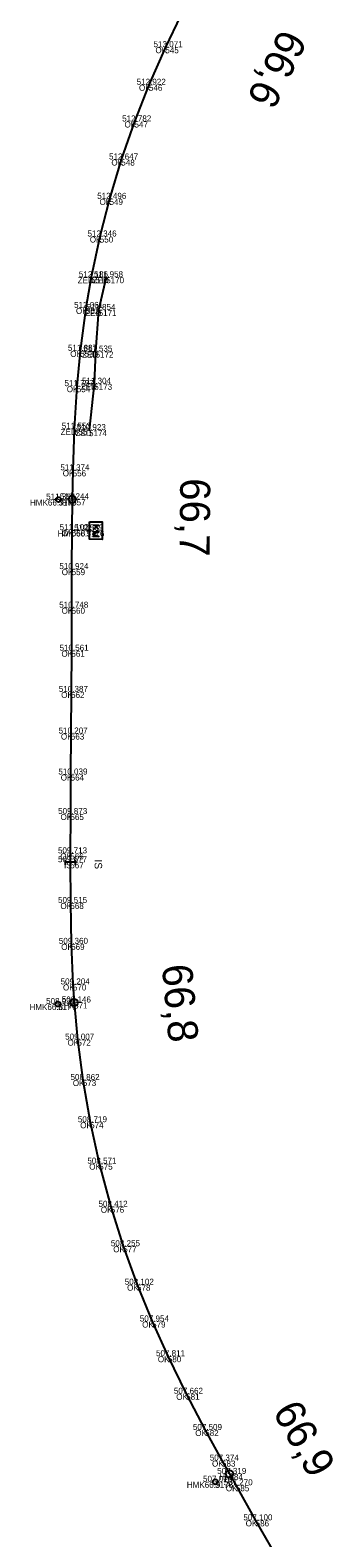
# Model space of a CAD drawing. Extents: x -621782 to -610392, y -1141853 to -1122321.
# Drawn here: x -621541.5 to -621480.9, y -1123820.3 to -1123519.4 of the extents above; entities that cross this region are included whole.
import ezdxf

# ---------------------------------------------------------------- set-up
doc = ezdxf.new("R2010")
doc.units = 0
for name, color, linetype in [('Vrstva 1', 7, 'Continuous'), ('Vrstva 13', 7, 'Continuous'), ('Vrstva 3', 7, 'Continuous'), ('Vrstva 60', 7, 'Continuous'), ('Vrstva 61', 7, 'Continuous'), ('Vrstva 62', 7, 'Continuous'), ('Vrstva 7', 7, 'Continuous')]:
    doc.layers.add(name, color=color, linetype=linetype)

msp = doc.modelspace()

# ---------------------------------------------------------------- linework, layer by layer
at = {"layer": 'Vrstva 1'}
msp.add_lwpolyline([(-621511.47, -1123516.54), (-621514.51, -1123522.8), (-621517.78, -1123530.3), (-621520.67, -1123537.63), (-621523.29, -1123545.22), (-621525.64, -1123553.07), (-621527.58, -1123560.59), (-621529.29, -1123568.71), (-621530.35, -1123574.84), (-621531.48, -1123583.41), (-621532.17, -1123590.46), (-621532.72, -1123598.98), (-621532.98, -1123607.26), (-621533.09, -1123613.05), (-621533.15, -1123619.2), (-621533.19, -1123626.98), (-621533.21, -1123634.69), (-621533.25, -1123643.27), (-621533.3, -1123651.49), (-621533.35, -1123659.8), (-621533.39, -1123667.98), (-621533.43, -1123675.87), (-621533.46, -1123683.72), (-621533.47, -1123685.49), (-621533.45, -1123693.62), (-621533.29, -1123701.78), (-621532.94, -1123709.88), (-621532.7, -1123713.48), (-621532.04, -1123720.89), (-621530.97, -1123728.96), (-621529.5, -1123737.38), (-621527.7, -1123745.65), (-621525.39, -1123754.26), (-621522.92, -1123762.13), (-621520.16, -1123769.81), (-621517.15, -1123777.16), (-621514.02, -1123784.08), (-621510.36, -1123791.59), (-621506.56, -1123798.82), (-621503.22, -1123804.92), (-621501.73, -1123807.58), (-621500.46, -1123809.84), (-621496.51, -1123816.85), (-621492.58, -1123823.83)], dxfattribs=at)
at = {"layer": 'Vrstva 13'}
msp.add_lwpolyline([(-621526.3, -1123568.71), (-621527.81, -1123575.26), (-621528.42, -1123583.55), (-621528.69, -1123589.99), (-621529.72, -1123599.24)], dxfattribs=at)
at = {"layer": 'Vrstva 3'}
for p, q in [((-621534.47, -1123684.99), (-621534.47, -1123685.99)), ((-621532.47, -1123685.48), (-621534.47, -1123685.49)), ((-621532.47, -1123684.98), (-621532.47, -1123685.98))]:
    msp.add_line(p, q, dxfattribs=at)
at = {"layer": 'Vrstva 60'}
for p, q in [((-621514.51, -1123522.8), (-621514.51, -1123522.8)), ((-621517.78, -1123530.3), (-621517.78, -1123530.3)), ((-621520.67, -1123537.63), (-621520.67, -1123537.63)), ((-621523.29, -1123545.22), (-621523.29, -1123545.22)), ((-621525.64, -1123553.07), (-621525.64, -1123553.07)), ((-621527.58, -1123560.59), (-621527.58, -1123560.59)), ((-621529.29, -1123568.71), (-621529.29, -1123568.71)), ((-621526.3, -1123568.71), (-621526.3, -1123568.71)), ((-621530.35, -1123574.84), (-621530.35, -1123574.84)), ((-621527.81, -1123575.26), (-621527.81, -1123575.26)), ((-621531.48, -1123583.41), (-621531.48, -1123583.41)), ((-621528.42, -1123583.55), (-621528.42, -1123583.55)), ((-621532.17, -1123590.46), (-621532.17, -1123590.46)), ((-621528.69, -1123589.99), (-621528.69, -1123589.99)), ((-621532.72, -1123598.98), (-621532.72, -1123598.98)), ((-621529.72, -1123599.24), (-621529.72, -1123599.24)), ((-621532.98, -1123607.26), (-621532.98, -1123607.26)), ((-621535.82, -1123613.09), (-621535.82, -1123613.09)), ((-621533.09, -1123613.05), (-621533.09, -1123613.05)), ((-621533.15, -1123619.2), (-621533.15, -1123619.2)), ((-621530.23, -1123619.27), (-621530.23, -1123619.27)), ((-621533.19, -1123626.98), (-621533.19, -1123626.98)), ((-621533.21, -1123634.69), (-621533.21, -1123634.69)), ((-621533.25, -1123643.27), (-621533.25, -1123643.27)), ((-621533.3, -1123651.49), (-621533.3, -1123651.49)), ((-621533.35, -1123659.8), (-621533.35, -1123659.8)), ((-621533.39, -1123667.98), (-621533.39, -1123667.98)), ((-621533.43, -1123675.87), (-621533.43, -1123675.87)), ((-621533.46, -1123683.72), (-621533.46, -1123683.72)), ((-621533.47, -1123685.49), (-621533.47, -1123685.49)), ((-621533.45, -1123693.62), (-621533.45, -1123693.62)), ((-621533.29, -1123701.78), (-621533.29, -1123701.78)), ((-621532.94, -1123709.88), (-621532.94, -1123709.88)), ((-621535.92, -1123713.79), (-621535.92, -1123713.79)), ((-621532.7, -1123713.48), (-621532.7, -1123713.48)), ((-621532.04, -1123720.89), (-621532.04, -1123720.89)), ((-621530.97, -1123728.96), (-621530.97, -1123728.96)), ((-621529.5, -1123737.38), (-621529.5, -1123737.38)), ((-621527.7, -1123745.65), (-621527.7, -1123745.65)), ((-621525.39, -1123754.26), (-621525.39, -1123754.26)), ((-621522.92, -1123762.13), (-621522.92, -1123762.13)), ((-621520.16, -1123769.81), (-621520.16, -1123769.81)), ((-621517.15, -1123777.16), (-621517.15, -1123777.16)), ((-621514.02, -1123784.08), (-621514.02, -1123784.08)), ((-621510.36, -1123791.59), (-621510.36, -1123791.59)), ((-621506.56, -1123798.82), (-621506.56, -1123798.82)), ((-621503.22, -1123804.92), (-621503.22, -1123804.92)), ((-621501.73, -1123807.58), (-621501.73, -1123807.58)), ((-621504.56, -1123809.16), (-621504.56, -1123809.16)), ((-621500.46, -1123809.84), (-621500.46, -1123809.84)), ((-621496.51, -1123816.85), (-621496.51, -1123816.85))]:
    msp.add_line(p, q, dxfattribs=at)
at = {"layer": 'Vrstva 7'}
for p, q in [((-621535.82, -1123613.04), (-621535.82, -1123613.14)), ((-621527.73, -1123618.27), (-621528.98, -1123618.26)), ((-621527.74, -1123619.1), (-621528.57, -1123618.27)), ((-621530.23, -1123619.27), (-621529.61, -1123619.28)), ((-621528.27, -1123618.57), (-621528.98, -1123619.1)), ((-621535.92, -1123713.74), (-621535.91, -1123713.84)), ((-621504.59, -1123809.12), (-621504.54, -1123809.21))]:
    msp.add_line(p, q, dxfattribs=at)
msp.add_lwpolyline([(-621529.6, -1123617.53), (-621527.11, -1123617.55), (-621527.13, -1123621.04), (-621529.61, -1123621.02)], close=True, dxfattribs=at)
msp.add_lwpolyline([(-621528.99, -1123619.51), (-621527.74, -1123619.52), (-621528.99, -1123619.99), (-621527.75, -1123620.47), (-621528.99, -1123620.46)], dxfattribs=at)
for centre, radius in [((-621533.09, -1123613.05), 0.75), ((-621535.82, -1123613.09), 0.5), ((-621535.92, -1123713.79), 0.5), ((-621532.7, -1123713.48), 0.75), ((-621501.73, -1123807.58), 0.75), ((-621504.56, -1123809.16), 0.5)]:
    msp.add_circle(centre, radius, dxfattribs=at)

# ---------------------------------------------------------------- texts
at = {"layer": 'Vrstva 3'}
msp.add_text('IS', height=1.5, rotation=270.169, dxfattribs=at).set_placement((-621528.62, -1123684.95))
at = {"layer": 'Vrstva 60'}
for s, p in [('545', (-621514.51, -1123524)), ('546', (-621517.78, -1123531.5)), ('547', (-621520.67, -1123538.83)), ('548', (-621523.29, -1123546.42)), ('549', (-621525.64, -1123554.27)), ('550', (-621527.58, -1123561.79)), ('551', (-621529.29, -1123569.91)), ('5170', (-621526.3, -1123569.91)), ('552', (-621530.35, -1123576.04)), ('5171', (-621527.81, -1123576.46)), ('553', (-621531.48, -1123584.61)), ('5172', (-621528.42, -1123584.75)), ('554', (-621532.17, -1123591.66)), ('5173', (-621528.69, -1123591.19)), ('555', (-621532.72, -1123600.18)), ('5174', (-621529.72, -1123600.44)), ('556', (-621532.98, -1123608.46)), ('5175', (-621535.82, -1123614.29)), ('557', (-621533.09, -1123614.25)), ('558', (-621533.15, -1123620.4)), ('5176', (-621530.23, -1123620.47)), ('559', (-621533.19, -1123628.18)), ('560', (-621533.21, -1123635.89)), ('561', (-621533.25, -1123644.47)), ('562', (-621533.3, -1123652.69)), ('563', (-621533.35, -1123661)), ('564', (-621533.39, -1123669.18)), ('565', (-621533.43, -1123677.07)), ('566', (-621533.46, -1123684.92)), ('567', (-621533.47, -1123686.69)), ('568', (-621533.45, -1123694.82)), ('569', (-621533.29, -1123702.98)), ('570', (-621532.94, -1123711.08)), ('5177', (-621535.92, -1123714.99)), ('571', (-621532.7, -1123714.68)), ('572', (-621532.04, -1123722.09)), ('573', (-621530.97, -1123730.16)), ('574', (-621529.5, -1123738.58)), ('575', (-621527.7, -1123746.85)), ('576', (-621525.39, -1123755.46)), ('577', (-621522.92, -1123763.33)), ('578', (-621520.16, -1123771.01)), ('579', (-621517.15, -1123778.36)), ('580', (-621514.02, -1123785.28)), ('581', (-621510.36, -1123792.79)), ('582', (-621506.56, -1123800.02)), ('583', (-621503.22, -1123806.12)), ('584', (-621501.73, -1123808.78)), ('5178', (-621504.56, -1123810.36)), ('585', (-621500.46, -1123811.04)), ('586', (-621496.51, -1123818.05))]:
    msp.add_text(s, height=1.2, dxfattribs=at).set_placement(p)
at = {"layer": 'Vrstva 61'}
for s, p in [('513.071', (-621516.87, -1123522.8)), ('512.922', (-621520.23, -1123530.3)), ('512.782', (-621523.12, -1123537.63)), ('512.647', (-621525.74, -1123545.22)), ('512.496', (-621528.09, -1123553.07)), ('512.346', (-621530.03, -1123560.59)), ('512.186', (-621531.75, -1123568.71)), ('511.958', (-621528.75, -1123568.71)), ('512.061', (-621532.71, -1123574.84)), ('511.854', (-621530.26, -1123575.26)), ('511.887', (-621533.93, -1123583.41)), ('511.535', (-621530.88, -1123583.55)), ('511.737', (-621534.62, -1123590.46)), ('511.304', (-621531.14, -1123589.99)), ('511.553', (-621535.17, -1123598.98)), ('510.923', (-621532.18, -1123599.24)), ('511.374', (-621535.44, -1123607.26)), ('511.354', (-621538.27, -1123613.09)), ('511.244', (-621535.54, -1123613.05)), ('511.102', (-621535.59, -1123619.2)), ('510.539', (-621532.68, -1123619.27)), ('510.924', (-621535.64, -1123626.98)), ('510.748', (-621535.67, -1123634.69)), ('510.561', (-621535.61, -1123643.27)), ('510.387', (-621535.75, -1123651.49)), ('510.207', (-621535.8, -1123659.8)), ('510.039', (-621535.84, -1123667.98)), ('509.873', (-621535.88, -1123675.87)), ('509.677', (-621535.92, -1123685.49)), ('509.713', (-621535.92, -1123683.72)), ('509.515', (-621535.91, -1123693.62)), ('509.360', (-621535.74, -1123701.78)), ('509.204', (-621535.39, -1123709.88)), ('508.931', (-621538.28, -1123713.79)), ('509.146', (-621535.15, -1123713.48)), ('509.007', (-621534.49, -1123720.89)), ('508.862', (-621533.42, -1123728.96)), ('508.719', (-621531.95, -1123737.38)), ('508.571', (-621530.06, -1123745.65)), ('508.412', (-621527.84, -1123754.26)), ('508.255', (-621525.37, -1123762.13)), ('508.102', (-621522.61, -1123769.81)), ('507.954', (-621519.6, -1123777.16)), ('507.811', (-621516.38, -1123784.08)), ('507.662', (-621512.81, -1123791.59)), ('507.509', (-621509.02, -1123798.82)), ('507.374', (-621505.67, -1123804.92)), ('507.010', (-621507.01, -1123809.16)), ('507.319', (-621504.18, -1123807.58)), ('507.270', (-621502.91, -1123809.84)), ('507.100', (-621498.96, -1123816.85))]:
    msp.add_text(s, height=1.2, dxfattribs=at).set_placement(p)
at = {"layer": 'Vrstva 62'}
for s, p in [('OK', (-621516.49, -1123524)), ('OK', (-621519.77, -1123531.5)), ('OK', (-621522.65, -1123538.83)), ('OK', (-621525.27, -1123546.42)), ('OK', (-621527.63, -1123554.27)), ('OK', (-621529.57, -1123561.79)), ('ZED', (-621531.97, -1123569.91)), ('ZED', (-621528.97, -1123569.91)), ('OK', (-621532.33, -1123576.04)), ('ZED', (-621530.48, -1123576.46)), ('OK', (-621533.47, -1123584.61)), ('ZED', (-621531.1, -1123584.75)), ('OK', (-621534.16, -1123591.66)), ('ZED', (-621531.36, -1123591.19)), ('ZED', (-621535.39, -1123600.18)), ('ZED', (-621532.4, -1123600.44)), ('OK', (-621534.97, -1123608.46)), ('HMK66.7', (-621541.49, -1123614.29)), ('HM', (-621535.12, -1123614.25)), ('HMC66.7', (-621535.97, -1123620.47)), ('OK', (-621535.13, -1123620.4)), ('OK', (-621535.17, -1123628.18)), ('OK', (-621535.2, -1123635.89)), ('OK', (-621535.23, -1123644.47)), ('OK', (-621535.28, -1123652.69)), ('OK', (-621535.33, -1123661)), ('OK', (-621535.37, -1123669.18)), ('OK', (-621535.41, -1123677.07)), ('OK', (-621535.45, -1123684.92)), ('IS', (-621534.7, -1123686.69)), ('OK', (-621535.43, -1123694.82)), ('OK', (-621535.27, -1123702.98)), ('OK', (-621534.92, -1123711.08)), ('HMK66.8', (-621541.59, -1123714.99)), ('HM', (-621534.73, -1123714.68)), ('OK', (-621534.02, -1123722.09)), ('OK', (-621532.96, -1123730.16)), ('OK', (-621531.48, -1123738.58)), ('OK', (-621529.68, -1123746.85)), ('OK', (-621527.37, -1123755.46)), ('OK', (-621524.9, -1123763.33)), ('OK', (-621522.14, -1123771.01)), ('OK', (-621519.13, -1123778.36)), ('OK', (-621516, -1123785.28)), ('OK', (-621512.34, -1123792.79)), ('OK', (-621508.55, -1123800.02)), ('OK', (-621505.21, -1123806.12)), ('HM', (-621503.76, -1123808.78)), ('HMK66.9', (-621510.23, -1123810.36)), ('OK', (-621502.44, -1123811.04)), ('OK', (-621498.5, -1123818.05))]:
    msp.add_text(s, height=1.2, dxfattribs=at).set_placement(p)
at = {"layer": 'Vrstva 7'}
for s, rotation, p in [('66,6', 244.1087, (-621491.48, -1123518.86)), ('66,7', 269.4874, (-621511.54, -1123608.81)), ('66,8', 275.0926, (-621515.21, -1123706.08)), ('66,9', 299.312, (-621493.24, -1123795.16))]:
    msp.add_text(s, height=6, rotation=rotation, dxfattribs=at).set_placement(p)

doc.saveas('drawing.dxf')
